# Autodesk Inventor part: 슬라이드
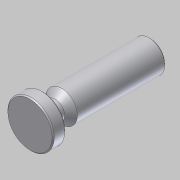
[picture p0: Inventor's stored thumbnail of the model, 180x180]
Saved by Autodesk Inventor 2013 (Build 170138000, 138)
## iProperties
Created: 2014-03
Part Number: 슬라이드
Document SubType Name: Modeling
Designer: SeoGD™[esajin.kr]
Density: 1 g/cm^3
Material: 일반
Author: SeoGD™[esajin.kr]
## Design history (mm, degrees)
sketch "스케치1"
  geometry: L1 (7.5, 114.5)-(7.5, 91.5) reference; L2 (13, 91)-(-13, 91) reference; L3 (0, 126)-(0, 69); L4 (0, 69)-(11, 69); L5 (11, 69)-(11, 75); L6 (11, 75)-(4.5, 75); L7 (4.5, 75)-(4.5, 81); L8 (4.5, 81)-(7.5, 84); L9 (7.5, 84)-(7.5, 126); L10 (7.5, 126)-(0, 126); 2 further points
  constraints: 18 end point, 4 parallel, 3 perpendicular, 1 collinear, 1 midpoint, 1 point on line, 1 vertical, 2 other
  dimensions: "d0" = 57 distance of L3.start L3.end; "d1" = 6 distance of L4.end L5.end; "d2" = 45 deg angle of L8 L7; "d3" = 9 diameter of L7 L3; "d4" = 15 distance from line of L4 L8.end; "d5" = 22 distance from line of L3.end L2; "d6" = 22 diameter of L5 L3
revolve "회전1" sketch "스케치1" stored, may be unused: angle "d7" = 90 deg
chamfer "모따기1" distance "d8" = 0.5; stored, may be unused: second distance "d9" = 2, angle "d10" = 45 deg
fillet "모깎기1" dims "d11" = 0.3
node "솔리드1"
node "참조1"
